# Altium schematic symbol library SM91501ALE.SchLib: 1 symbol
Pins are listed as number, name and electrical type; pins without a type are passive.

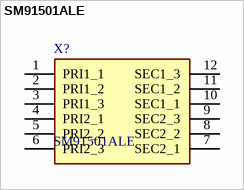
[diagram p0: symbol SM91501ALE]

## SM91501ALE
designator X?
Audio Transformers / Signal Transformers BMS xformer 2-Ch 1600V AECQ +125 C; Manufacturer_Name: Bourns; Geometry.Height: 5mm
footprint SOP200P1473X500-12N
pins: 1 PRI1_1, 2 PRI1_2, 3 PRI1_3, 4 PRI2_1, 5 PRI2_2, 6 PRI2_3, 7 SEC2_1, 8 SEC2_2, 9 SEC2_3, 10 SEC1_1, 11 SEC1_2, 12 SEC1_3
